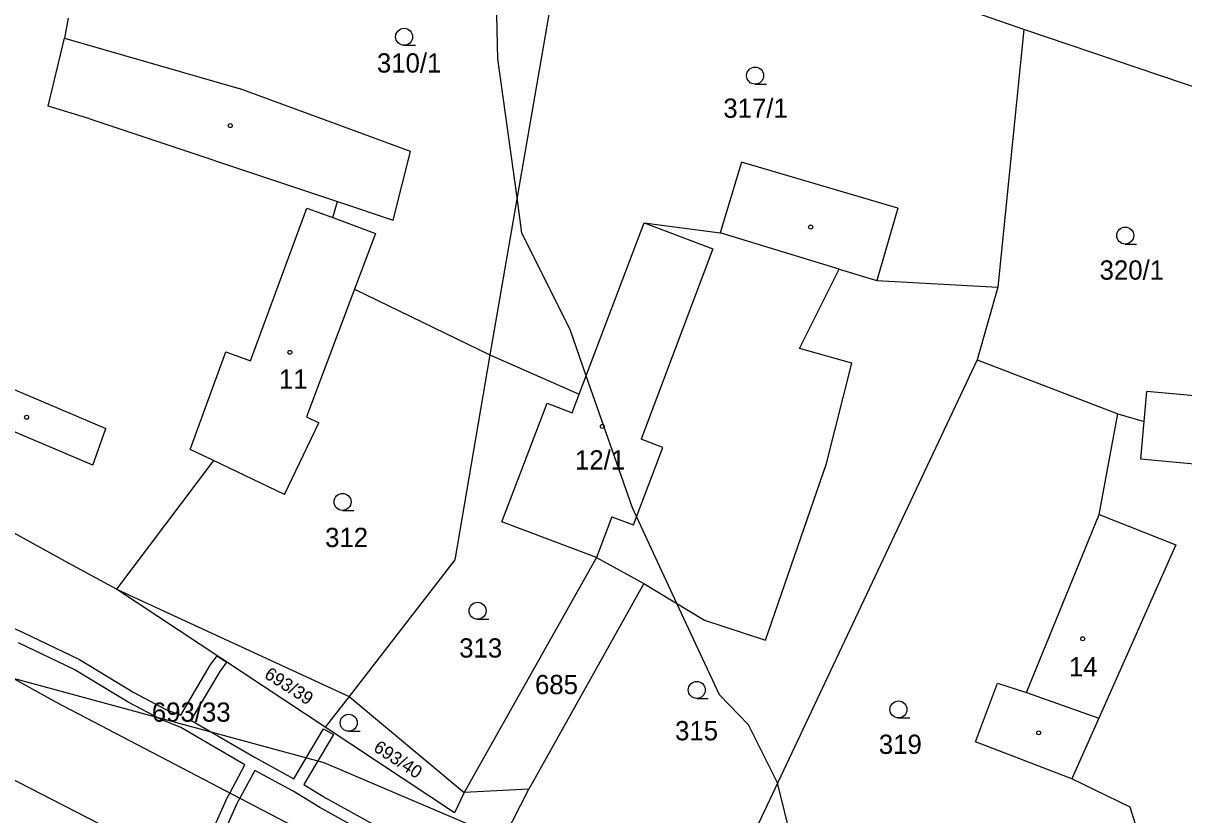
# Model space of a CAD drawing. Extents: x -747333 to -745433, y -1133152 to -1130600.
# Drawn here: x -746327.1 to -746224.7, y -1132085.5 to -1132015.6 of the extents above; entities that cross this region are included whole.
import ezdxf

# ---------------------------------------------------------------- set-up
doc = ezdxf.new("R2010")
doc.units = 0
for name, color, linetype in [('Vrstva 1', 7, 'Continuous'), ('Vrstva 18', 7, 'Continuous'), ('Vrstva 19', 7, 'Continuous'), ('Vrstva 25', 7, 'Continuous'), ('Vrstva 3', 7, 'Continuous'), ('Vrstva 30', 7, 'Continuous'), ('Vrstva 37', 7, 'Continuous'), ('Vrstva 4', 7, 'Continuous'), ('Vrstva 52', 7, 'Continuous')]:
    doc.layers.add(name, color=color, linetype=linetype)

msp = doc.modelspace()

# ---------------------------------------------------------------- linework, layer by layer
at = {"layer": 'Vrstva 1'}
for points in [[(-746279.37, -1132007.17), (-746285.89, -1132044.86)], [(-746238.77, -1132016.17), (-746246.82, -1132013.34)], [(-746323.11, -1132015.17), (-746323.42, -1132016.94)], [(-746238.77, -1132016.17), (-746241.07, -1132038.89)], [(-746220.77, -1132022.26), (-746238.77, -1132016.17)], [(-746323.42, -1132016.94), (-746308.01, -1132021.36)], [(-746298.15, -1132024.98), (-746308.01, -1132021.36)], [(-746292.91, -1132026.93), (-746298.15, -1132024.98)], [(-746294.44, -1132032.99), (-746292.91, -1132026.93)], [(-746263.7, -1132027.87), (-746265.57, -1132034.1)], [(-746249.89, -1132031.93), (-746263.7, -1132027.87)], [(-746299.76, -1132032.76), (-746299.33, -1132031.35)], [(-746299.33, -1132031.35), (-746294.44, -1132032.99)], [(-746249.89, -1132031.93), (-746251.76, -1132038.31)], [(-746299.76, -1132032.76), (-746295.97, -1132034.16)], [(-746278, -1132048.33), (-746272.28, -1132033.23)], [(-746272.28, -1132033.23), (-746265.57, -1132034.1)], [(-746295.97, -1132034.16), (-746297.83, -1132039.08)], [(-746258.57, -1132044.32), (-746255.07, -1132037.3)], [(-746255.07, -1132037.3), (-746251.76, -1132038.31)], [(-746297.83, -1132039.08), (-746302.08, -1132050.35)], [(-746297.83, -1132039.08), (-746285.89, -1132044.86)], [(-746251.76, -1132038.31), (-746241.07, -1132038.89)], [(-746241.07, -1132038.89), (-746242.88, -1132045.31)], [(-746285.89, -1132044.86), (-746288.99, -1132062.95)], [(-746285.89, -1132044.86), (-746278, -1132048.33)], [(-746253.96, -1132045.62), (-746258.57, -1132044.32)], [(-746242.88, -1132045.31), (-746262.42, -1132086.72)], [(-746256.19, -1132054.45), (-746253.96, -1132045.62)], [(-746242.88, -1132045.31), (-746230.47, -1132050.07)], [(-746324.12, -1132075.54), (-746374.84, -1132047.38)], [(-746278.63, -1132049.98), (-746278, -1132048.33)], [(-746228.16, -1132050.76), (-746227.92, -1132048.11)], [(-746215.96, -1132049.2), (-746227.92, -1132048.11)], [(-746284.85, -1132059.6), (-746280.85, -1132049.13)], [(-746280.85, -1132049.13), (-746278.63, -1132049.98)], [(-746302.08, -1132050.35), (-746300.98, -1132050.87)], [(-746232.13, -1132058.95), (-746230.47, -1132050.07)], [(-746230.47, -1132050.07), (-746228.16, -1132050.76)], [(-746304, -1132057.19), (-746300.98, -1132050.87)], [(-746310.27, -1132054.2), (-746318.84, -1132065.55)], [(-746304, -1132057.19), (-746310.27, -1132054.2)], [(-746261.56, -1132070.05), (-746256.19, -1132054.45)], [(-746323.01, -1132063.27), (-746333.61, -1132057.47)], [(-746238.55, -1132074.67), (-746232.13, -1132058.95)], [(-746276.47, -1132062.76), (-746284.85, -1132059.6)], [(-746317.29, -1132087.85), (-746364.32, -1132063.67)], [(-746318.84, -1132065.55), (-746323.01, -1132063.27)], [(-746288.99, -1132062.95), (-746298.31, -1132075)], [(-746276.47, -1132062.76), (-746288.15, -1132083.49)], [(-746276.47, -1132062.76), (-746272.31, -1132065.05)], [(-746300.43, -1132077.73), (-746318.84, -1132065.55)], [(-746318.84, -1132065.55), (-746298.31, -1132075)], [(-746272.31, -1132065.05), (-746282.45, -1132083.18)], [(-746272.31, -1132065.05), (-746266.94, -1132068.28)], [(-746266.94, -1132068.28), (-746261.56, -1132070.05)], [(-746243.03, -1132079.01), (-746241.1, -1132073.85)], [(-746241.1, -1132073.85), (-746238.55, -1132074.67)], [(-746282.49, -1132097.32), (-746324.12, -1132075.54)], [(-746298.31, -1132075), (-746300.43, -1132077.73)], [(-746298.31, -1132075), (-746288.15, -1132083.49)], [(-746289.02, -1132085.27), (-746300.43, -1132077.73)], [(-746234.55, -1132082.27), (-746243.03, -1132079.01)], [(-746229.39, -1132084.77), (-746234.55, -1132082.27)], [(-746288.15, -1132083.49), (-746289.02, -1132085.27)], [(-746282.45, -1132083.18), (-746288.15, -1132083.49)], [(-746285.29, -1132088.71), (-746282.45, -1132083.18)], [(-746228.31, -1132088.24), (-746229.39, -1132084.77)]]:
    msp.add_lwpolyline(points, dxfattribs=at)
at = {"layer": 'Vrstva 25'}
for p, q in [((-746293.46, -1132017.56), (-746292.46, -1132017.56)), ((-746262.49, -1132020.99), (-746261.49, -1132020.99)), ((-746229.83, -1132035.1), (-746228.83, -1132035.1)), ((-746298.89, -1132058.6), (-746297.89, -1132058.6)), ((-746286.98, -1132068.2), (-746285.98, -1132068.2)), ((-746267.63, -1132075.19), (-746266.63, -1132075.19)), ((-746249.84, -1132076.91), (-746248.84, -1132076.91)), ((-746298.35, -1132078.08), (-746297.35, -1132078.08))]:
    msp.add_line(p, q, dxfattribs=at)
for centre, radius in [((-746293.46, -1132016.81), 0.75), ((-746262.49, -1132020.24), 0.75), ((-746308.8, -1132024.65), 0.174503), ((-746257.59, -1132033.6), 0.174503), ((-746229.83, -1132034.35), 0.75), ((-746303.54, -1132044.65), 0.174503), ((-746326.77, -1132050.38), 0.174503), ((-746275.97, -1132051.19), 0.174503), ((-746298.89, -1132057.85), 0.75), ((-746286.98, -1132067.45), 0.75), ((-746233.58, -1132069.92), 0.174503), ((-746267.63, -1132074.44), 0.75), ((-746249.84, -1132076.16), 0.75), ((-746298.35, -1132077.33), 0.75), ((-746237.47, -1132078.22), 0.174503)]:
    msp.add_circle(centre, radius, dxfattribs=at)
at = {"layer": 'Vrstva 3'}
for points in [[(-746307.02, -1132045.4), (-746302.05, -1132031.92)], [(-746302.05, -1132031.92), (-746299.76, -1132032.76)], [(-746299.76, -1132032.76), (-746295.97, -1132034.16)], [(-746278, -1132048.33), (-746272.28, -1132033.23)], [(-746272.28, -1132033.23), (-746266.23, -1132035.52)], [(-746295.97, -1132034.16), (-746297.83, -1132039.08)], [(-746266.23, -1132035.52), (-746272.55, -1132052.32)], [(-746297.83, -1132039.08), (-746302.08, -1132050.35)], [(-746312.34, -1132053.21), (-746309.18, -1132044.61)], [(-746309.18, -1132044.61), (-746307.02, -1132045.4)], [(-746278.63, -1132049.98), (-746278, -1132048.33)], [(-746284.85, -1132059.6), (-746280.85, -1132049.13)], [(-746280.85, -1132049.13), (-746278.63, -1132049.98)], [(-746302.08, -1132050.35), (-746300.98, -1132050.87)], [(-746304, -1132057.19), (-746300.98, -1132050.87)], [(-746270.64, -1132053.04), (-746272.55, -1132052.32)], [(-746310.27, -1132054.2), (-746312.34, -1132053.21)], [(-746273.21, -1132059.87), (-746270.64, -1132053.04)], [(-746304, -1132057.19), (-746310.27, -1132054.2)], [(-746275.12, -1132059.16), (-746276.47, -1132062.76)], [(-746275.12, -1132059.16), (-746273.21, -1132059.87)], [(-746238.55, -1132074.67), (-746232.13, -1132058.95)], [(-746232.13, -1132058.95), (-746225.35, -1132061.62)], [(-746276.47, -1132062.76), (-746284.85, -1132059.6)], [(-746225.35, -1132061.62), (-746232.17, -1132076.93)], [(-746238.55, -1132074.67), (-746232.17, -1132076.93)]]:
    msp.add_lwpolyline(points, dxfattribs=at)
at = {"layer": 'Vrstva 30'}
for points in [[(-746331.46, -1132067.44), (-746327.07, -1132069.37)], [(-746327.07, -1132069.37), (-746322.11, -1132071.74)], [(-746322.58, -1132072.62), (-746327.49, -1132070.29)], [(-746322.11, -1132071.74), (-746317.31, -1132074.66)], [(-746310.57, -1132072.26), (-746309.96, -1132071.43)], [(-746309.96, -1132071.43), (-746309.12, -1132071.98)], [(-746317.81, -1132075.52), (-746322.58, -1132072.62)], [(-746313.16, -1132076.67), (-746310.57, -1132072.26)], [(-746309.73, -1132072.81), (-746312.27, -1132077.11)], [(-746309.12, -1132071.98), (-746309.73, -1132072.81)], [(-746317.31, -1132074.66), (-746314.49, -1132076.15)], [(-746314.91, -1132077.05), (-746317.81, -1132075.52)], [(-746314.49, -1132076.15), (-746313.16, -1132076.67)], [(-746313.17, -1132077.74), (-746314.91, -1132077.05)], [(-746307.51, -1132081.04), (-746313.17, -1132077.74)], [(-746312.27, -1132077.11), (-746306.59, -1132080.41)], [(-746303.18, -1132082.27), (-746300.56, -1132077.86)], [(-746300.56, -1132077.86), (-746299.7, -1132078.37)], [(-746299.7, -1132078.37), (-746302.32, -1132082.77)], [(-746308.85, -1132083.53), (-746307.51, -1132081.04)], [(-746306.59, -1132080.41), (-746303.18, -1132082.27)], [(-746306.64, -1132081.53), (-746307.97, -1132083.99)], [(-746303.25, -1132083.37), (-746306.64, -1132081.53)], [(-746302.32, -1132082.77), (-746300.41, -1132083.95)], [(-746310.87, -1132087.97), (-746309.08, -1132083.95)], [(-746309.08, -1132083.95), (-746308.85, -1132083.53)], [(-746307.97, -1132083.99), (-746308.18, -1132084.39)], [(-746300.91, -1132084.81), (-746303.25, -1132083.37)], [(-746300.41, -1132083.95), (-746294.53, -1132087.2)], [(-746308.18, -1132084.39), (-746309.95, -1132088.37)], [(-746295.01, -1132088.08), (-746300.91, -1132084.81)]]:
    msp.add_lwpolyline(points, dxfattribs=at)
at = {"layer": 'Vrstva 37'}
for centre in [(-746303.54, -1132044.65), (-746275.97, -1132051.19), (-746233.58, -1132069.92)]:
    msp.add_circle(centre, 0.174503, dxfattribs=at)
at = {"layer": 'Vrstva 4'}
for points in [[(-746324.88, -1132022.93), (-746323.42, -1132016.94)], [(-746321.19, -1132024.04), (-746324.88, -1132022.93)], [(-746321.19, -1132024.04), (-746299.33, -1132031.35)], [(-746307.02, -1132045.4), (-746302.05, -1132031.92)], [(-746302.05, -1132031.92), (-746299.76, -1132032.76)], [(-746272.28, -1132033.23), (-746266.23, -1132035.52)], [(-746255.07, -1132037.3), (-746265.57, -1132034.1)], [(-746266.23, -1132035.52), (-746272.55, -1132052.32)], [(-746312.34, -1132053.21), (-746309.18, -1132044.61)], [(-746309.18, -1132044.61), (-746307.02, -1132045.4)], [(-746332.24, -1132046.07), (-746319.78, -1132051.38)], [(-746320.94, -1132054.61), (-746332.67, -1132049.65)], [(-746320.94, -1132054.61), (-746319.78, -1132051.38)], [(-746228.46, -1132054.09), (-746228.16, -1132050.76)], [(-746270.64, -1132053.04), (-746272.55, -1132052.32)], [(-746310.27, -1132054.2), (-746312.34, -1132053.21)], [(-746273.21, -1132059.87), (-746270.64, -1132053.04)], [(-746216.5, -1132055.18), (-746228.46, -1132054.09)], [(-746275.12, -1132059.16), (-746276.47, -1132062.76)], [(-746275.12, -1132059.16), (-746273.21, -1132059.87)], [(-746232.13, -1132058.95), (-746225.35, -1132061.62)], [(-746225.35, -1132061.62), (-746232.17, -1132076.93)], [(-746238.55, -1132074.67), (-746232.17, -1132076.93)], [(-746232.17, -1132076.93), (-746234.55, -1132082.27)]]:
    msp.add_lwpolyline(points, dxfattribs=at)
at = {"layer": 'Vrstva 52'}
for points in [[(-746259.25, -1132087.75), (-746260.5, -1132082.64), (-746263.06, -1132077.5), (-746265.63, -1132074.88), (-746269.38, -1132066.81), (-746273.31, -1132058.38), (-746277.39, -1132046.71), (-746278.81, -1132042.63), (-746283.06, -1132034.13), (-746283.49, -1132031), (-746285.19, -1132018.75), (-746285.49, -1132005.98), (-746285.63, -1132000.5), (-746285.59, -1132000), (-746285.52, -1131999.06), (-746284.7, -1131987.34), (-746283.94, -1131976.49), (-746283.51, -1131970.33), (-746283.5, -1131970.25), (-746281.77, -1131962.03), (-746281.38, -1131960.12), (-746281.38, -1131948.63)], [(-746246.5, -1132108.12), (-746247.65, -1132107.5), (-746266, -1132097.53), (-746282.63, -1132088.5), (-746284.72, -1132087.61), (-746300.5, -1132080.87), (-746327.94, -1132073.42), (-746328.56, -1132073.25), (-746347.25, -1132069.88), (-746350.56, -1132070.74), (-746411.94, -1132086.88), (-746415.94, -1132087.47), (-746420.08, -1132088.64), (-746420.35, -1132088.38), (-746424.25, -1132089.37), (-746427.25, -1132089), (-746438.31, -1132090.25), (-746447.63, -1132090.8)]]:
    msp.add_lwpolyline(points, dxfattribs=at)

# ---------------------------------------------------------------- texts
at = {"layer": 'Vrstva 18'}
for s, p in [('310/1', (-746295.86, -1132019.97)), ('317/1', (-746265.29, -1132023.96)), ('320/1', (-746232.09, -1132038.24)), ('312', (-746300.43, -1132061.83)), ('313', (-746288.6, -1132071.58)), ('685', (-746281.91, -1132074.81)), ('693/33', (-746315.72, -1132077.24)), ('315', (-746269.55, -1132078.88)), ('319', (-746251.57, -1132080.08))]:
    msp.add_text(s, height=1.7, dxfattribs=at).set_placement(p)
for s, rotation, p in [('693/39', 327.44997, (-746305.88, -1132073.31)), ('693/40', 326.76048, (-746296.25, -1132079.76))]:
    msp.add_text(s, height=1.14, rotation=rotation, dxfattribs=at).set_placement(p)
at = {"layer": 'Vrstva 19'}
for s, p in [('11', (-746304.5, -1132047.85)), ('12/1', (-746278.38, -1132054.99)), ('14', (-746234.8, -1132073.24))]:
    msp.add_text(s, height=1.7, dxfattribs=at).set_placement(p)

doc.saveas('drawing.dxf')
